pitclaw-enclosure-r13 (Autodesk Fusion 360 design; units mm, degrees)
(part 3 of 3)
create_component "CreateComponent8"
create_component "CreateComponent9"
create_component "CreateComponent10"
create_component "CreateComponent11"
create_component "CreateComponent12"
create_component "CreateComponent13"
create_component "CreateComponent7"
create_component "CreateComponent1"
create_component "CreateComponent2"
create_component "CreateComponent3"
create_component "CreateComponent4"
create_component "CreateComponent5"
create_component "CreateComponent6"
create_component "CreateComponent7"
create_component "CreateComponent8"
create_component "CreateComponent9"
create_component "CreateComponent10"
create_component "CreateComponent11"
create_component "CreateComponent12"
create_component "CreateComponent13"
create_component "CreateComponent14"
create_component "CreateComponent15"
create_component "CreateComponent16"
create_component "CreateComponent17"
create_component "CreateComponent18"
create_component "CreateComponent8"
create_component "CreateComponent9"
named bodies: "01 Bottom shell", "02 Top bezel - fitted lip and 4.2mm pilots", "03 WT32 retainer - four anchors", "Carrier PCB - placed components omitted", "WT32 nominal envelope - sample verification required", "01 Bottom shell - fitted guides and 4.2mm pilots", "C1 electrolytic sleeve", "C1 aluminum top", "C1 leads", "C1 leads (1)", "C3 electrolytic sleeve", "C3 aluminum top", "C3 leads", "C3 leads (1)", "C2 ceramic body", "C2 leads", "C2 leads (1)", "C4 ceramic body", "C4 leads", "C4 leads (1)", "C10 ceramic body", "C10 leads", "C10 leads (1)", "C11 ceramic body", "C11 leads", "C11 leads (1)", "C12 ceramic body", "C12 leads", "C12 leads (1)", "K1 relay case", "K1 leads", "K1 leads (1)", "K1 leads (2)", "K1 leads (3)", "K1 leads (4)", "U2 converter case", "U2 leads", "U2 leads (1)", "U2 leads (2)", "Q1 insulating support", "Q1 metal tab", "Q1 molded body", "Q1 bent lead 1", "Q1 lead tail 1", "Q1 bent lead 2", "Q1 lead tail 2", "Q1 bent lead 3", "Q1 lead tail 3", "BZ1 piezo housing", "BZ1 leads", "BZ1 leads (1)", "J2 RJ45 housing", "J2 contact 1", "J2 contact 2", "J2 contact 3", "J2 contact 4", "J2 contact 5", "J2 contact 6", "J2 contact 7", "J2 contact 8"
